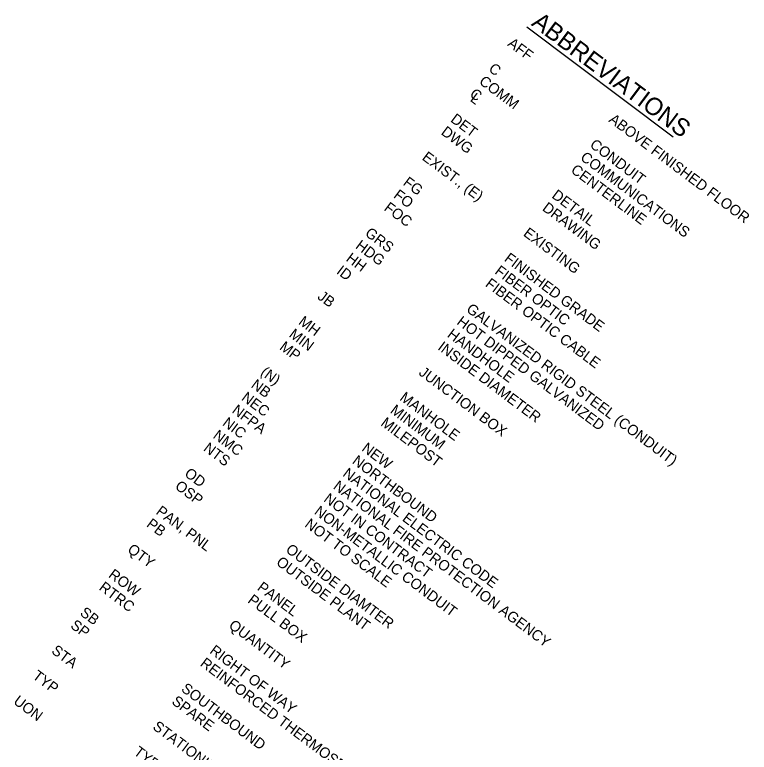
# Model space of a CAD drawing. Extents: x 626494 to 628870, y 365986 to 369334.
# Drawn here: x 628003 to 628253.6, y 368584.2 to 368835.9 of the extents above; entities that cross this region are included whole.
import ezdxf

# ---------------------------------------------------------------- set-up
doc = ezdxf.new("R2010")
doc.units = 0
doc.layers.add('R_Shade Frontage Road', color=7, linetype='Continuous')

msp = doc.modelspace()

# ---------------------------------------------------------------- linework, layer by layer
at = {"layer": 'R_Shade Frontage Road'}
msp.add_line((628177.68, 368831.77), (628227.63, 368794.27), dxfattribs=at)

# ---------------------------------------------------------------- texts
for s, height, p in [('ABBREVIATIONS', 6, (628178.99, 368832.47)), ('AFF', 3.6, (628170.89, 368825.52)), ('C', 3.6, (628164.41, 368816.88)), ('COMM', 3.6, (628161.17, 368812.56)), ('L', 3.6, (628158.13, 368806.64)), ('C', 3.6, (628157.95, 368808.23)), ('DET', 3.6, (628151.44, 368799.61)), ('ABOVE FINISHED FLOOR', 3.6, (628205.44, 368799.58)), ('DWG', 3.6, (628148.2, 368795.29)), ('CONDUIT', 3.6, (628198.95, 368790.94)), ('EXIST., (E)', 3.6, (628141.71, 368786.65)), ('COMMUNICATIONS ', 3.6, (628195.71, 368786.62)), ('CENTERLINE', 3.6, (628192.47, 368782.31)), ('FG', 3.6, (628135.23, 368778.02)), ('FO', 3.6, (628131.98, 368773.7)), ('DETAIL', 3.6, (628185.98, 368773.67)), ('FOC', 3.6, (628128.74, 368769.38)), ('DRAWING', 3.6, (628182.74, 368769.35)), ('GRS', 3.6, (628122.26, 368760.75)), ('EXISTING', 3.6, (628176.26, 368760.71)), ('HDG', 3.6, (628119.01, 368756.43)), ('HH', 3.6, (628115.77, 368752.11)), ('FINISHED GRADE', 3.6, (628169.77, 368752.08)), ('ID', 3.6, (628112.53, 368747.79)), ('FIBER OPTIC', 3.6, (628166.53, 368747.76)), ('FIBER OPTIC CABLE', 3.6, (628163.29, 368743.44)), ('JB', 3.6, (628106.04, 368739.16)), ('GALVANIZED RIGID STEEL (CONDUIT)', 3.6, (628156.8, 368734.81)), ('MH', 3.6, (628099.56, 368730.52)), ('HOT DIPPED GALVANIZED', 3.6, (628153.56, 368730.49)), ('MIN', 3.6, (628096.32, 368726.2)), ('HANDHOLE', 3.6, (628150.32, 368726.17)), ('MP', 3.6, (628093.07, 368721.88)), ('INSIDE DIAMETER', 3.6, (628147.07, 368721.85)), ('(N)', 3.6, (628086.59, 368713.25)), ('JUNCTION BOX', 3.6, (628140.59, 368713.22)), ('NB', 3.6, (628083.35, 368708.93)), ('NEC', 3.6, (628080.1, 368704.61)), ('MANHOLE', 3.6, (628134.1, 368704.58)), ('NFPA', 3.6, (628076.86, 368700.29)), ('MINIMUM', 3.6, (628130.86, 368700.26)), ('NIC', 3.6, (628073.62, 368695.97)), ('MILEPOST', 3.6, (628127.62, 368695.94)), ('NMC', 3.6, (628070.38, 368691.66)), ('NTS', 3.6, (628067.13, 368687.34)), ('NEW', 3.6, (628121.13, 368687.31)), ('NORTHBOUND', 3.6, (628117.89, 368682.99)), ('OD', 3.6, (628060.65, 368678.7)), ('NATIONAL ELECTRIC CODE', 3.6, (628114.65, 368678.67)), ('OSP', 3.6, (628057.41, 368674.38)), ('NATIONAL FIRE PROTECTION AGENCY', 3.6, (628111.41, 368674.35)), ('NOT IN CONTRACT', 3.6, (628108.16, 368670.03)), ('PAN, PNL', 3.6, (628050.92, 368665.75)), ('NON-METALLIC CONDUIT', 3.6, (628104.92, 368665.72)), ('PB', 3.6, (628047.68, 368661.43)), ('NOT TO SCALE', 3.6, (628101.68, 368661.4)), ('QTY', 3.6, (628041.19, 368652.79)), ('OUTSIDE DIAMTER', 3.6, (628095.19, 368652.76)), ('OUTSIDE PLANT', 3.6, (628091.95, 368648.44)), ('ROW', 3.6, (628034.71, 368644.16)), ('RTRC', 3.6, (628031.47, 368639.84)), ('PANEL', 3.6, (628085.47, 368639.81)), ('PULL BOX', 3.6, (628082.22, 368635.49)), ('SB', 3.6, (628024.98, 368631.2)), ('SP', 3.6, (628021.74, 368626.88)), ('QUANTITY', 3.6, (628075.74, 368626.85)), ('STA', 3.6, (628015.25, 368618.25)), ('RIGHT OF WAY', 3.6, (628069.25, 368618.22)), ('REINFORCED THERMOSETTING RESIN CONDUIT', 3.6, (628066.01, 368613.9)), ('TYP', 3.6, (628008.77, 368609.61)), ('SOUTHBOUND', 3.6, (628059.53, 368605.26)), ('UON', 3.6, (628002.28, 368600.98)), ('SPARE', 3.6, (628056.28, 368600.94)), ('STATIONING', 3.6, (628049.8, 368592.31)), ('TYPICAL', 3.6, (628043.31, 368583.67))]:
    msp.add_text(s, height=height, rotation=323.0968, dxfattribs=at).set_placement(p)

doc.saveas('drawing.dxf')
